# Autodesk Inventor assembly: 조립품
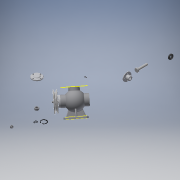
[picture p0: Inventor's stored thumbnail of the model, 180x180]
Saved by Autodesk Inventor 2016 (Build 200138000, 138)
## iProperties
Created: 2017-01
Part Number: 조립품
Material: 일반
Document SubType Name: Assembly
Designer: Administrator
Author: Administrator
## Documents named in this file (19)
- C:\Users\Administrator\Desktop\470130V1002\470130V1002\조립품.iam
- C:\Users\Administrator\Desktop\470130V1002\470130V1002\V-벨트풀리.ipt
- C:\Users\Administrator\Desktop\470130V1002\470130V1002\너트 M8.ipt
- C:\Users\Administrator\Desktop\470130V1002\470130V1002\뒤커버.ipt
- C:\Users\Administrator\Desktop\470130V1002\470130V1002\멈춤링- 15 x 1.ipt
- C:\Users\Administrator\Desktop\470130V1002\470130V1002\멈춤링- 35x1.6.ipt
- KS B 1336 - 35x1.6.ipt
- C:\Users\Administrator\Desktop\470130V1002\470130V1002\베어링- 6202.ipt
- KS B 2023 - 6202 - 15 x 35 x 11 - 7.8.ipt
- C:\Users\Administrator\Desktop\470130V1002\470130V1002\본체.ipt
- C:\Users\Administrator\Desktop\470130V1002\470130V1002\볼트 M4 x 12.ipt
- C:\Users\Administrator\Desktop\470130V1002\470130V1002\볼트 M4 x 16.ipt
- C:\Users\Administrator\Desktop\470130V1002\470130V1002\부시.ipt
- C:\Users\Administrator\Desktop\470130V1002\470130V1002\상부커버.ipt
- C:\Users\Administrator\Desktop\470130V1002\470130V1002\슬라이드.ipt
- C:\Users\Administrator\Desktop\470130V1002\470130V1002\앞커버.ipt
- C:\Users\Administrator\Desktop\470130V1002\470130V1002\오일실 15 30 7.ipt
- C:\Users\Administrator\Desktop\470130V1002\470130V1002\키 4 x 4 x 12.ipt
- C:\Users\Administrator\Desktop\470130V1002\470130V1002\편심축.ipt
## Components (8 placed, 5 different names)
1. V-벨트풀리:1
2. KS B 1336 - 35x1.6:1
3. KS B 2023 - 6202 - 15 x 35 x 11 - 7.8:1
4. KS B 1021 - 에 따름 ISO 1207 - 미터 A  M 4 x 12:1
5. ISO 4762 M4 x 16:1
6. ISO 4762 M4 x 16:2
7. ISO 4762 M4 x 16:3
8. ISO 4762 M4 x 16:4
